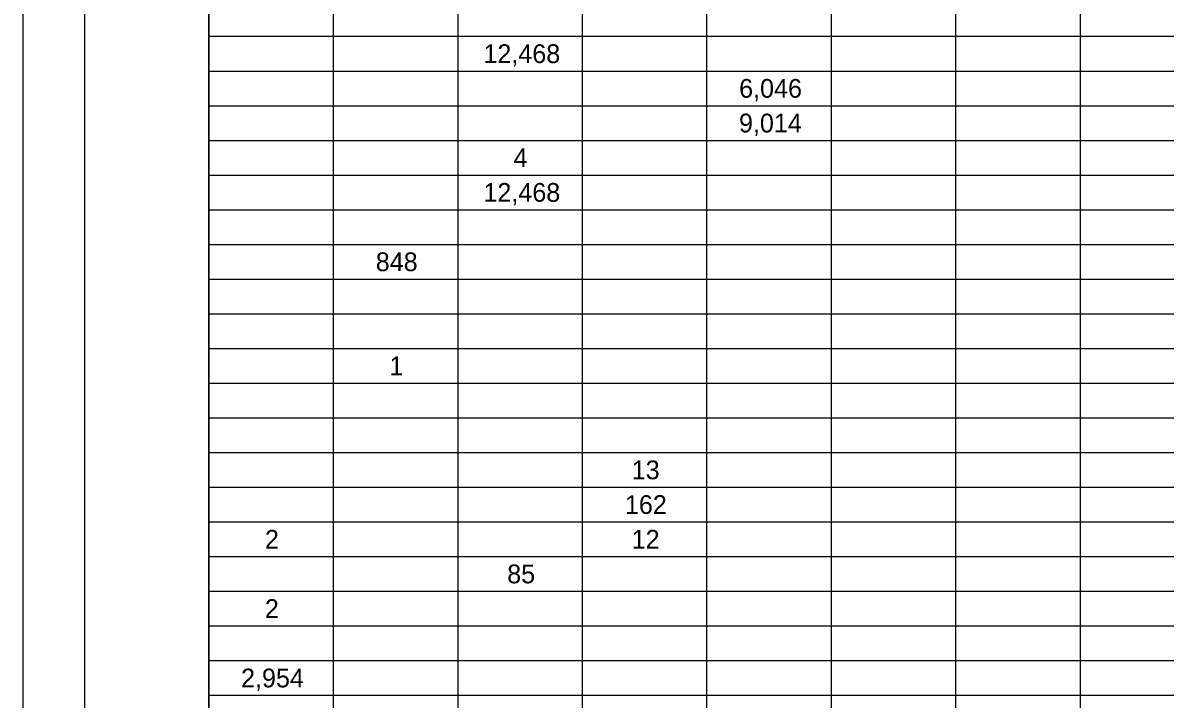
# Model space of a CAD drawing. Extents: x 0 to 34, y 0 to 22.
# Drawn here: x 0 to 9.22, y 11.11 to 16.57 of the extents above; entities that cross this region are included whole.
import ezdxf

# ---------------------------------------------------------------- set-up
doc = ezdxf.new("R2010")
doc.units = 0
for name, color, linetype in [('SH_Border', 7, 'Continuous'), ('SH_Cut_Line', 7, 'Continuous'), ('SH_Text', 7, 'Continuous')]:
    doc.layers.add(name, color=color, linetype=linetype)

msp = doc.modelspace()

# ---------------------------------------------------------------- linework, layer by layer
at = {"layer": 'SH_Border'}
for points in [[(0.5, 21.5), (1.5, 21.5), (1.5, 0.5), (0.5, 0.5)], [(1.5, 21.5), (33.5, 21.5), (33.5, 0.5), (1.5, 0.5)]]:
    msp.add_lwpolyline(points, close=True, dxfattribs=at)
at = {"layer": 'SH_Cut_Line'}
msp.add_lwpolyline([(0, 0), (34, 0), (34, 22), (0, 22)], close=True, dxfattribs=at)
at = {"layer": 'SH_Text'}
for p, q in [((1.5, 21.5), (1.5, 0.5)), ((2.5046, 20.94), (2.5046, 0.5)), ((3.5092, 20.94), (3.5092, 0.5)), ((4.5138, 20.94), (4.5138, 0.5)), ((5.5184, 20.94), (5.5184, 0.5)), ((6.5229, 20.94), (6.5229, 0.5)), ((7.5275, 20.94), (7.5275, 0.5)), ((8.5321, 20.94), (8.5321, 0.5)), ((1.5, 16.46), (32, 16.46)), ((1.5, 16.18), (32, 16.18)), ((1.5, 15.9), (32, 15.9)), ((1.5, 15.62), (32, 15.62)), ((1.5, 15.34), (32, 15.34)), ((1.5, 15.06), (32, 15.06)), ((1.5, 14.78), (32, 14.78)), ((1.5, 14.5), (32, 14.5)), ((1.5, 14.22), (32, 14.22)), ((1.5, 13.94), (32, 13.94)), ((1.5, 13.66), (32, 13.66)), ((1.5, 13.38), (32, 13.38)), ((1.5, 13.1), (32, 13.1)), ((1.5, 12.82), (32, 12.82)), ((1.5, 12.54), (32, 12.54)), ((1.5, 12.26), (32, 12.26)), ((1.5, 11.98), (32, 11.98)), ((1.5, 11.7), (32, 11.7)), ((1.5, 11.42), (32, 11.42)), ((1.5, 11.14), (32, 11.14))]:
    msp.add_line(p, q, dxfattribs=at)

# ---------------------------------------------------------------- texts
for s, height, p in [('12,468', 0.15153, (3.717, 16.2442)), ('6,046', 0.15153, (5.7804, 15.9642)), ('9,014', 0.15153, (5.7792, 15.6842)), ('4', 0.1515, (3.9601, 15.4042)), ('12,468', 0.15153, (3.717, 15.1242)), ('848', 0.15153, (2.8481, 14.5642)), ('1', 0.1515, (2.9583, 13.7242)), ('13', 0.15153, (4.9138, 12.8842)), ('162', 0.15153, (4.8588, 12.6042)), ('2', 0.1515, (1.9538, 12.3242)), ('12', 0.15153, (4.9132, 12.3242)), ('85', 0.15153, (3.9089, 12.0442)), ('2', 0.1515, (1.9538, 11.7642)), ('2,954', 0.15153, (1.7609, 11.2042))]:
    msp.add_text(s, height=height, dxfattribs=at).set_placement(p)

doc.saveas('drawing.dxf')
